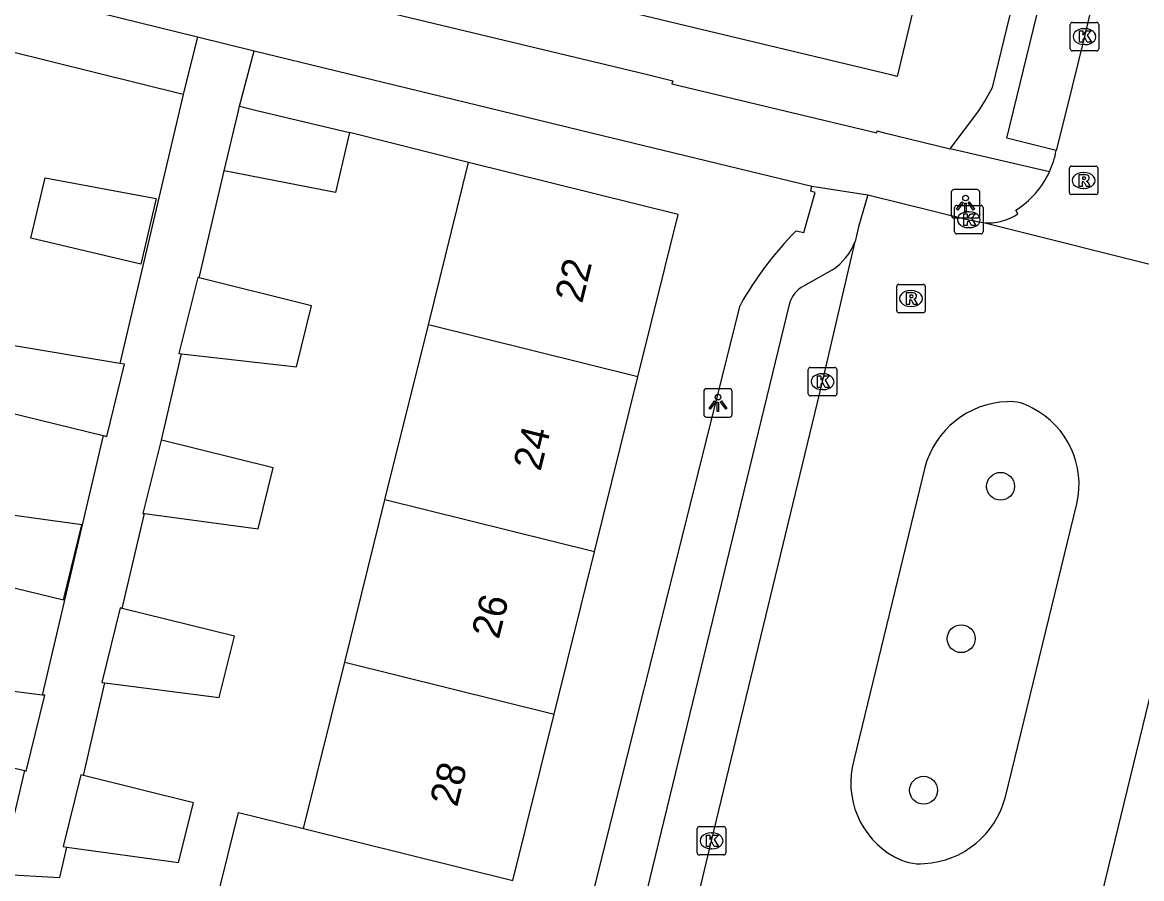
# Model space of a CAD drawing. Extents: x 162812 to 163818, y 381639 to 382470.
# Drawn here: x 163102.96 to 163142.25, y 382223.04 to 382253.1 of the extents above; entities that cross this region are included whole.
import ezdxf

# ---------------------------------------------------------------- set-up
doc = ezdxf.new("R2010")
doc.units = 0
for name, color, linetype in [('IMGEO_Boom', 7, 'Continuous'), ('IMGEO_Erf', 7, 'Continuous'), ('IMGEO_Kolk', 7, 'Continuous'), ('IMGEO_Lichtpunt', 7, 'Continuous'), ('IMGEO_Pand', 7, 'Continuous'), ('IMGEO_Pand_nummerreeks', 7, 'Continuous'), ('IMGEO_Rijbaan_lokaal_open', 7, 'Continuous'), ('IMGEO_Rioolput', 7, 'Continuous'), ('IMGEO_Voetpad_open', 7, 'Continuous')]:
    doc.layers.add(name, color=color, linetype=linetype)

msp = doc.modelspace()

# ---------------------------------------------------------------- linework, layer by layer
at = {"layer": 'IMGEO_Boom'}
for centre in [(163137.294, 382236.817), (163135.913, 382231.467), (163134.592, 382226.148)]:
    msp.add_circle(centre, 0.489, dxfattribs=at)
at = {"layer": 'IMGEO_Erf'}
for points in [[(163108.604, 382250.569), (163100.863, 382252.485)], [(163118.626, 382248.182), (163114.449, 382249.237)]]:
    msp.add_lwpolyline(points, dxfattribs=at)
at = {"layer": 'IMGEO_Kolk'}
for p, q in [((163139.741, 382252.177), (163139.741, 382253.029)), ((163139.816, 382253.103), (163140.668, 382253.103)), ((163140.229, 382252.883), (163140.254, 382252.883)), ((163140.742, 382253.029), (163140.742, 382252.177)), ((163140.668, 382252.103), (163139.816, 382252.103)), ((163140.252, 382252.323), (163140.227, 382252.323)), ((163135.683, 382245.751), (163135.683, 382246.603)), ((163135.758, 382246.677), (163136.61, 382246.677)), ((163136.684, 382246.603), (163136.684, 382245.751)), ((163136.171, 382246.457), (163136.196, 382246.457)), ((163136.194, 382245.897), (163136.169, 382245.897)), ((163136.61, 382245.677), (163135.758, 382245.677)), ((163130.548, 382240.065), (163130.548, 382240.917)), ((163130.623, 382240.991), (163131.475, 382240.991)), ((163131.036, 382240.771), (163131.061, 382240.771)), ((163131.549, 382240.917), (163131.549, 382240.065)), ((163131.475, 382239.991), (163130.623, 382239.991)), ((163131.059, 382240.211), (163131.034, 382240.211)), ((163126.652, 382223.948), (163126.652, 382224.8)), ((163126.727, 382224.874), (163127.579, 382224.874)), ((163127.14, 382224.654), (163127.165, 382224.654)), ((163127.653, 382224.8), (163127.653, 382223.948)), ((163127.579, 382223.874), (163126.727, 382223.874)), ((163127.163, 382224.094), (163127.138, 382224.094))]:
    msp.add_line(p, q, dxfattribs=at)
for points in [[(163139.741, 382252.177), (163139.741, 382253.029)], [(163139.816, 382253.103), (163140.668, 382253.103)], [(163140.742, 382253.029), (163140.742, 382252.177)], [(163140.062, 382252.803), (163140.185, 382252.803), (163140.185, 382252.652), (163140.315, 382252.803), (163140.479, 382252.803), (163140.333, 382252.652), (163140.486, 382252.403), (163140.334, 382252.403), (163140.249, 382252.567), (163140.185, 382252.5), (163140.185, 382252.403), (163140.062, 382252.403), (163140.062, 382252.803)], [(163140.668, 382252.103), (163139.816, 382252.103)], [(163135.683, 382245.751), (163135.683, 382246.603)], [(163135.758, 382246.677), (163136.61, 382246.677)], [(163136.684, 382246.603), (163136.684, 382245.751)], [(163136.004, 382246.377), (163136.127, 382246.377), (163136.127, 382246.226), (163136.257, 382246.377), (163136.421, 382246.377), (163136.275, 382246.226), (163136.428, 382245.977), (163136.276, 382245.977), (163136.191, 382246.141), (163136.127, 382246.074), (163136.127, 382245.977), (163136.004, 382245.977), (163136.004, 382246.377)], [(163136.61, 382245.677), (163135.758, 382245.677)], [(163130.548, 382240.065), (163130.548, 382240.917)], [(163130.623, 382240.991), (163131.475, 382240.991)], [(163130.869, 382240.691), (163130.992, 382240.691), (163130.992, 382240.54), (163131.122, 382240.691), (163131.286, 382240.691), (163131.14, 382240.54), (163131.293, 382240.291), (163131.141, 382240.291), (163131.056, 382240.455), (163130.992, 382240.388), (163130.992, 382240.291), (163130.869, 382240.291), (163130.869, 382240.691)], [(163131.549, 382240.917), (163131.549, 382240.065)], [(163131.475, 382239.991), (163130.623, 382239.991)], [(163126.652, 382223.948), (163126.652, 382224.8)], [(163126.727, 382224.874), (163127.579, 382224.874)], [(163126.973, 382224.574), (163127.096, 382224.574), (163127.096, 382224.423), (163127.226, 382224.574), (163127.39, 382224.574), (163127.244, 382224.423), (163127.397, 382224.174), (163127.245, 382224.174), (163127.16, 382224.338), (163127.096, 382224.271), (163127.096, 382224.174), (163126.973, 382224.174), (163126.973, 382224.574)], [(163127.653, 382224.8), (163127.653, 382223.948)], [(163127.579, 382223.874), (163126.727, 382223.874)]]:
    msp.add_lwpolyline(points, dxfattribs=at)
for centre, start, end in [((163139.818, 382253.027), 91.552, 178.448), ((163139.818, 382253.027), 91.552, 178.448), ((163140.666, 382253.027), 1.552, 88.448), ((163140.666, 382253.027), 1.552, 88.448), ((163139.818, 382252.179), 181.552, 268.448), ((163139.818, 382252.179), 181.552, 268.448), ((163140.666, 382252.179), 271.552, 358.448), ((163140.666, 382252.179), 271.552, 358.448), ((163135.76, 382246.601), 91.552, 178.448), ((163135.76, 382246.601), 91.552, 178.448), ((163136.608, 382246.601), 1.552, 88.448), ((163136.608, 382246.601), 1.552, 88.448), ((163135.76, 382245.753), 181.552, 268.448), ((163135.76, 382245.753), 181.552, 268.448), ((163136.608, 382245.753), 271.552, 358.448), ((163136.608, 382245.753), 271.552, 358.448), ((163130.625, 382240.915), 91.552, 178.448), ((163130.625, 382240.915), 91.552, 178.448), ((163131.473, 382240.915), 1.552, 88.448), ((163131.473, 382240.915), 1.552, 88.448), ((163130.625, 382240.067), 181.552, 268.448), ((163130.625, 382240.067), 181.552, 268.448), ((163131.473, 382240.067), 271.552, 358.448), ((163131.473, 382240.067), 271.552, 358.448), ((163126.729, 382224.798), 91.552, 178.448), ((163126.729, 382224.798), 91.552, 178.448), ((163127.577, 382224.798), 1.552, 88.448), ((163127.577, 382224.798), 1.552, 88.448), ((163126.729, 382223.95), 181.552, 268.448), ((163126.729, 382223.95), 181.552, 268.448), ((163127.577, 382223.95), 271.552, 358.448), ((163127.577, 382223.95), 271.552, 358.448)]:
    msp.add_arc(centre, 0.0765, start, end, dxfattribs=at)
for centre, major_axis, ratio, start_param, end_param in [((163140.228, 382252.603), (-0.387, 0.002), 0.722429, 4.712389, 7.853982), ((163140.253, 382252.603), (-0.39, 0.002), 0.717154, 1.570796, 4.712389), ((163136.17, 382246.177), (-0.387, 0.002), 0.722429, 4.712389, 7.853982), ((163136.195, 382246.177), (-0.39, 0.002), 0.717154, 1.570796, 4.712389), ((163131.035, 382240.491), (-0.387, 0.002), 0.722429, 4.712389, 7.853982), ((163131.06, 382240.491), (-0.39, 0.002), 0.717154, 1.570796, 4.712389), ((163127.139, 382224.374), (-0.387, 0.002), 0.722429, 4.712389, 7.853982), ((163127.164, 382224.374), (-0.39, 0.002), 0.717154, 1.570796, 4.712389)]:
    msp.add_ellipse(centre, major_axis=major_axis, ratio=ratio, start_param=start_param, end_param=end_param, dxfattribs=at)
at = {"layer": 'IMGEO_Lichtpunt'}
for p, q in [((163135.567, 382247.14), (163135.567, 382246.333)), ((163135.567, 382247.14), (163135.567, 382246.333)), ((163136.469, 382247.235), (163135.661, 382247.235)), ((163136.469, 382247.235), (163135.661, 382247.235)), ((163136.563, 382246.333), (163136.563, 382247.14)), ((163136.563, 382246.333), (163136.563, 382247.14)), ((163135.661, 382246.239), (163136.469, 382246.239)), ((163135.661, 382246.239), (163136.469, 382246.239)), ((163126.878, 382240.149), (163126.878, 382239.342)), ((163126.878, 382240.149), (163126.878, 382239.342)), ((163127.78, 382240.244), (163126.972, 382240.244)), ((163127.78, 382240.244), (163126.972, 382240.244)), ((163127.874, 382239.342), (163127.874, 382240.149)), ((163127.874, 382239.342), (163127.874, 382240.149)), ((163126.972, 382239.248), (163127.78, 382239.248)), ((163126.972, 382239.248), (163127.78, 382239.248))]:
    msp.add_line(p, q, dxfattribs=at)
for points in [[(163135.941, 382246.804), (163135.98, 382246.776), (163135.792, 382246.514), (163135.754, 382246.541), (163135.941, 382246.804)], [(163136.043, 382246.756), (163136.09, 382246.756), (163136.09, 382246.434), (163136.043, 382246.434), (163136.043, 382246.756)], [(163136.153, 382246.776), (163136.191, 382246.803), (163136.378, 382246.541), (163136.339, 382246.513), (163136.153, 382246.776)], [(163127.252, 382239.813), (163127.291, 382239.785), (163127.103, 382239.523), (163127.065, 382239.55), (163127.252, 382239.813)], [(163127.354, 382239.765), (163127.401, 382239.765), (163127.401, 382239.443), (163127.354, 382239.443), (163127.354, 382239.765)], [(163127.464, 382239.785), (163127.502, 382239.812), (163127.689, 382239.55), (163127.65, 382239.522), (163127.464, 382239.785)]]:
    msp.add_lwpolyline(points, dxfattribs=at)
for centre in [(163136.066, 382246.938), (163127.377, 382239.947)]:
    msp.add_circle(centre, 0.0994, dxfattribs=at)
for centre, start, end in [((163135.661, 382247.14), 90, 180), ((163135.661, 382247.14), 90, 180), ((163136.469, 382247.14), 0, 90), ((163136.469, 382247.14), 0, 90), ((163135.661, 382246.333), 180, 270), ((163135.661, 382246.333), 180, 270), ((163136.469, 382246.333), 270, 0), ((163136.469, 382246.333), 270, 360), ((163126.972, 382240.149), 90, 180), ((163126.972, 382240.149), 90, 180), ((163127.78, 382240.149), 0, 90), ((163127.78, 382240.149), 0, 90), ((163126.972, 382239.342), 180, 270), ((163126.972, 382239.342), 180, 270), ((163127.78, 382239.342), 270, 0), ((163127.78, 382239.342), 270, 360)]:
    msp.add_arc(centre, 0.0946, start, end, dxfattribs=at)
at = {"layer": 'IMGEO_Pand'}
for points in [[(163135.102, 382257.214), (163133.662, 382251.208), (163133.442, 382251.261), (163126.251, 382252.986), (163122.54, 382253.876), (163123.982, 382259.89), (163124.451, 382259.778)], [(163110.043, 382247.894), (163110.545, 382250), (163110.582, 382250.157)], [(163110.582, 382250.157), (163111.242, 382250), (163114.449, 382249.237)], [(163114.449, 382249.237), (163113.948, 382247.127), (163110.043, 382247.894)], [(163117.212, 382242.481), (163118.626, 382248.182)], [(163124.569, 382240.655), (163125.984, 382246.357), (163118.626, 382248.182)], [(163107.115, 382244.612), (163103.258, 382245.529), (163103.761, 382247.643), (163107.663, 382246.92), (163107.115, 382244.612)], [(163109.168, 382244.13), (163109.117, 382244.143), (163108.455, 382241.474), (163108.548, 382241.464)], [(163108.548, 382241.464), (163112.586, 382241.016), (163113.115, 382243.151), (163109.168, 382244.13)], [(163115.689, 382236.341), (163117.212, 382242.481)], [(163124.569, 382240.655), (163117.212, 382242.481)], [(163106.389, 382241.125), (163102.463, 382241.778), (163101.918, 382239.544), (163105.796, 382238.598)], [(163105.796, 382238.598), (163105.928, 382238.566), (163106.546, 382241.099), (163106.389, 382241.125)], [(163123.046, 382234.515), (163124.569, 382240.655)], [(163107.843, 382238.433), (163107.832, 382238.436), (163107.194, 382235.865), (163107.244, 382235.858)], [(163107.244, 382235.858), (163111.239, 382235.329), (163111.768, 382237.46), (163107.843, 382238.433)], [(163101.14, 382236.002), (163100.593, 382233.758), (163104.406, 382232.828), (163105.049, 382235.468), (163101.14, 382236.002)], [(163114.276, 382230.644), (163115.689, 382236.341)], [(163123.046, 382234.515), (163115.689, 382236.341)], [(163121.633, 382228.819), (163123.046, 382234.515)], [(163106.471, 382232.532), (163106.401, 382232.549), (163105.751, 382229.927), (163105.862, 382229.913)], [(163105.862, 382229.913), (163109.87, 382229.401), (163110.405, 382231.555), (163106.471, 382232.532)], [(163112.826, 382224.799), (163114.276, 382230.644)], [(163114.276, 382230.644), (163121.633, 382228.819)], [(163103.66, 382229.49), (163099.653, 382229.998), (163099.115, 382227.792), (163103.038, 382226.835)], [(163103.038, 382226.835), (163103.1, 382226.82), (163103.748, 382229.479), (163103.66, 382229.49)], [(163120.183, 382222.974), (163121.633, 382228.819)], [(163105.106, 382226.662), (163105.014, 382226.685), (163104.39, 382224.17), (163104.522, 382224.152)], [(163104.522, 382224.152), (163108.448, 382223.605), (163108.968, 382225.704), (163105.106, 382226.662)], [(163111.314, 382218.702), (163111.353, 382218.859), (163109.073, 382219.425), (163110.546, 382225.365), (163112.826, 382224.799)], [(163112.826, 382224.799), (163120.183, 382222.974)]]:
    msp.add_lwpolyline(points, dxfattribs=at)
at = {"layer": 'IMGEO_Rijbaan_lokaal_open'}
for points in [[(163141.812, 382259.252), (163140.24, 382252.604), (163139.594, 382250), (163139.247, 382248.603)], [(163132.637, 382247.045), (163132.31, 382245.931), (163132.188, 382245.406)], [(163132.637, 382247.045), (163136.184, 382246.175), (163136.382, 382246.138)], [(163137.906, 382246.387), (163137.828, 382246.507)], [(163136.694, 382246.075), (163143.569, 382244.359)], [(163126.177, 382220.3), (163127.154, 382224.374), (163131.05, 382240.49), (163132.188, 382245.406)], [(163145.726, 382242.413), (163144.32, 382236.804), (163140.443, 382220.841), (163139.498, 382217.076), (163137.595, 382217.507), (163127.997, 382219.832), (163126.177, 382220.3)], [(163134.638, 382237.481), (163132.148, 382227.198)], [(163137.465, 382225.917), (163139.971, 382236.202)]]:
    msp.add_lwpolyline(points, dxfattribs=at)
for centre, radius, start, end in [((163136.207, 382249.156), 3.09, 335.2036, 349.6936), ((163136.153, 382249.167), 3.143, 302.1926, 335.4295), ((163136.886, 382247.84), 1.776, 263.7994, 305.0725), ((163136.919, 382247.993), 1.931, 253.8567, 263.3116), ((163137.644, 382236.677), 3.112, 92.1882, 165.0199), ((163137.638, 382238.373), 1.418, 56.6478, 94.5863), ((163137.047, 382236.886), 3.003, 346.8415, 62.8365), ((163134.995, 382226.402), 2.956, 164.378, 241.2288), ((163134.437, 382226.69), 3.125, 273.367, 345.671), ((163134.471, 382225.329), 1.764, 239.3539, 274.8724)]:
    msp.add_arc(centre, radius, start, end, dxfattribs=at)
at = {"layer": 'IMGEO_Rioolput'}
for p, q in [((163139.71, 382247.13), (163139.71, 382247.982)), ((163139.785, 382248.056), (163140.637, 382248.056)), ((163140.198, 382247.836), (163140.223, 382247.836)), ((163140.711, 382247.982), (163140.711, 382247.13)), ((163140.637, 382247.056), (163139.785, 382247.056)), ((163140.221, 382247.276), (163140.196, 382247.276)), ((163133.65, 382242.981), (163133.65, 382243.833)), ((163133.725, 382243.907), (163134.577, 382243.907)), ((163134.651, 382243.833), (163134.651, 382242.981)), ((163134.138, 382243.687), (163134.163, 382243.687)), ((163134.161, 382243.127), (163134.136, 382243.127)), ((163134.577, 382242.907), (163133.725, 382242.907))]:
    msp.add_line(p, q, dxfattribs=at)
for points in [[(163139.71, 382247.13), (163139.71, 382247.982)], [(163139.785, 382248.056), (163140.637, 382248.056)], [(163140.299, 382247.754), (163140.047, 382247.756), (163140.047, 382247.356)], [(163140.711, 382247.982), (163140.711, 382247.13)], [(163140.047, 382247.356), (163140.171, 382247.356), (163140.171, 382247.518), (163140.182, 382247.518)], [(163140.225, 382247.675), (163140.171, 382247.675), (163140.171, 382247.594)], [(163140.171, 382247.594), (163140.223, 382247.594)], [(163140.229, 382247.489), (163140.3, 382247.356), (163140.44, 382247.356), (163140.375, 382247.482)], [(163140.637, 382247.056), (163139.785, 382247.056)], [(163133.65, 382242.981), (163133.65, 382243.833)], [(163133.725, 382243.907), (163134.577, 382243.907)], [(163134.651, 382243.833), (163134.651, 382242.981)], [(163134.239, 382243.605), (163133.987, 382243.607), (163133.987, 382243.207)], [(163134.165, 382243.526), (163134.111, 382243.526), (163134.111, 382243.445)], [(163134.111, 382243.445), (163134.163, 382243.445)], [(163133.987, 382243.207), (163134.111, 382243.207), (163134.111, 382243.369), (163134.122, 382243.369)], [(163134.169, 382243.34), (163134.24, 382243.207), (163134.38, 382243.207), (163134.315, 382243.333)], [(163134.577, 382242.907), (163133.725, 382242.907)]]:
    msp.add_lwpolyline(points, dxfattribs=at)
for centre, radius, start, end in [((163139.787, 382247.98), 0.0765, 91.552, 178.448), ((163139.787, 382247.98), 0.0765, 91.552, 178.448), ((163140.298, 382247.644), 0.109, 350.3612, 89.416), ((163140.635, 382247.98), 0.0765, 1.552, 88.448), ((163140.635, 382247.98), 0.0765, 1.552, 88.448), ((163140.181, 382247.465), 0.0533, 26.0293, 88.6989), ((163140.207, 382247.783), 0.19, 274.7715, 282.9687), ((163140.231, 382247.579), 0.0964, 77.0061, 93.1865), ((163140.245, 382247.636), 0.0378, 276.6634, 79.6772), ((163140.296, 382247.644), 0.112, 277.5842, 350.9817), ((163140.28, 382247.429), 0.108, 29.5134, 73.7905), ((163139.787, 382247.132), 0.0765, 181.552, 268.448), ((163139.787, 382247.132), 0.0765, 181.552, 268.448), ((163140.635, 382247.132), 0.0765, 271.552, 358.448), ((163140.635, 382247.132), 0.0765, 271.552, 358.448), ((163133.727, 382243.831), 0.0765, 91.552, 178.448), ((163133.727, 382243.831), 0.0765, 91.552, 178.448), ((163134.575, 382243.831), 0.0765, 1.552, 88.448), ((163134.575, 382243.831), 0.0765, 1.552, 88.448), ((163134.147, 382243.634), 0.19, 274.7715, 282.9687), ((163134.171, 382243.43), 0.0964, 77.0061, 93.1865), ((163134.185, 382243.487), 0.0378, 276.6634, 79.6772), ((163134.238, 382243.495), 0.109, 350.3612, 89.416), ((163134.236, 382243.495), 0.112, 277.5842, 350.9817), ((163134.121, 382243.316), 0.0533, 26.0293, 88.6989), ((163134.22, 382243.28), 0.108, 29.5134, 73.7905), ((163133.727, 382242.983), 0.0765, 181.552, 268.448), ((163133.727, 382242.983), 0.0765, 181.552, 268.448), ((163134.575, 382242.983), 0.0765, 271.552, 358.448), ((163134.575, 382242.983), 0.0765, 271.552, 358.448)]:
    msp.add_arc(centre, radius, start, end, dxfattribs=at)
for centre, major_axis, ratio, start_param, end_param in [((163140.197, 382247.556), (-0.387, 0.002), 0.722429, 4.712389, 7.853982), ((163140.222, 382247.556), (-0.39, 0.002), 0.717154, 1.570796, 4.712389), ((163134.137, 382243.407), (-0.387, 0.002), 0.722429, 4.712389, 7.853982), ((163134.162, 382243.407), (-0.39, 0.002), 0.717154, 1.570796, 4.712389)]:
    msp.add_ellipse(centre, major_axis=major_axis, ratio=ratio, start_param=start_param, end_param=end_param, dxfattribs=at)
at = {"layer": 'IMGEO_Voetpad_open'}
for points in [[(163135.523, 382248.664), (163136.536, 382250), (163136.747, 382250.336), (163137.011, 382250.814), (163151.17, 382309.066), (163147.739, 382309.906)], [(163139.247, 382248.603), (163137.515, 382249.041), (163137.748, 382250), (163140.099, 382259.655), (163141.812, 382259.252)], [(163090.093, 382257.281), (163109.113, 382252.594)], [(163113.517, 382254.008), (163124.858, 382251.282), (163125.788, 382251.054), (163125.763, 382250.951), (163132.954, 382249.227), (163132.969, 382249.291), (163133.177, 382249.24), (163135.523, 382248.664)], [(163109.113, 382252.594), (163108.604, 382250.569)], [(163109.113, 382252.594), (163111.102, 382252.11)], [(163110.582, 382250.157), (163111.102, 382252.11)], [(163111.102, 382252.11), (163119.771, 382250), (163122.549, 382249.324), (163130.671, 382247.351)], [(163108.604, 382250.569), (163106.389, 382241.125)], [(163139.012, 382247.86), (163135.523, 382248.664)], [(163109.168, 382244.13), (163110.043, 382247.894)], [(163130.126, 382245.787), (163130.388, 382245.731), (163130.783, 382247.133), (163130.637, 382247.179), (163130.671, 382247.351)], [(163130.671, 382247.351), (163132.637, 382247.045)], [(163131.394, 382244.422), (163130.38, 382243.842)], [(163121.429, 382216.275), (163128.151, 382243.17)], [(163129.89, 382243.252), (163124.878, 382222.632)], [(163107.843, 382238.433), (163108.548, 382241.464)], [(163105.796, 382238.598), (163103.66, 382229.49)], [(163106.471, 382232.532), (163107.244, 382235.858)], [(163105.106, 382226.662), (163105.862, 382229.913)], [(163103.038, 382226.835), (163102.186, 382223.204), (163104.275, 382223.089), (163104.522, 382224.152)]]:
    msp.add_lwpolyline(points, dxfattribs=at)
for centre, radius, start, end in [((163138.783, 382237.2), 12.193, 135.2324, 150.6853), ((163130.279, 382246.134), 2.043, 303.0758, 339.1234), ((163130.829, 382242.97), 0.98, 117.2659, 163.3143)]:
    msp.add_arc(centre, radius, start, end, dxfattribs=at)

# ---------------------------------------------------------------- texts
at = {"layer": 'IMGEO_Pand_nummerreeks'}
for s, p in [('22', (163122.607, 382243.211)), ('24', (163121.145, 382237.318)), ('26', (163119.683, 382231.422)), ('28', (163118.22, 382225.529))]:
    msp.add_text(s, height=1, rotation=76.0681, dxfattribs=at).set_placement(p)

doc.saveas('drawing.dxf')
